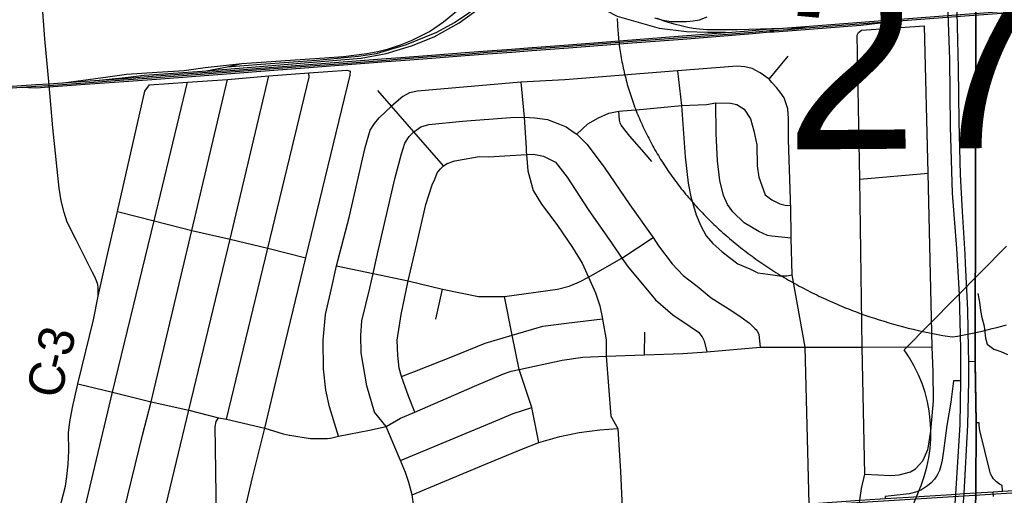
# Model space of a CAD drawing. Extents: x 114604 to 551442, y 316898 to 567001.
# Drawn here: x 164762 to 173075, y 383476 to 387495 of the extents above; entities that cross this region are included whole.
import ezdxf

# ---------------------------------------------------------------- set-up
doc = ezdxf.new("R2010")
doc.units = 0
for name, color, linetype in [('GE_P_Alignment', 7, 'Continuous'), ('GE_P_Alignment_1000_Bearings', 7, 'Continuous'), ('GE_P_Alignment_1000_Cardinal_Points', 7, 'Continuous'), ('GE_P_Alignment_1000_Stations', 7, 'Continuous'), ('GE_P_Alignment_500_Bearings', 7, 'Continuous'), ('GE_P_Alignment_500_Cardinal_Points', 7, 'Continuous'), ('GE_P_Alignment_500_Distances', 7, 'Continuous'), ('GE_P_Alignment_500_Stations', 7, 'Continuous'), ('PM_P_Cells', 7, 'Continuous'), ('PM_P_CL_Double_Solid', 7, 'Continuous'), ('PM_X_Stop_Line', 7, 'Continuous')]:
    doc.layers.add(name, color=color, linetype=linetype)

msp = doc.modelspace()

# ---------------------------------------------------------------- linework, layer by layer
at = {"layer": 'GE_P_Alignment'}
for points in [[(169807.1, 387505.3), (169807.7, 387487.8), (169808.3, 387470.3), (169809.1, 387452.8), (169810.1, 387435.4), (169811.2, 387417.9), (169812.4, 387400.4), (169813.7, 387382.9), (169815.2, 387365.4), (169816.8, 387347.9), (169818.6, 387330.4), (169820.5, 387312.9), (169822.5, 387295.5), (169824.7, 387278), (169827, 387260.5), (169829.5, 387243.1), (169832.1, 387225.6), (169834.8, 387208.2), (169837.7, 387190.7), (169840.7, 387173.3), (169843.8, 387155.9), (169847.1, 387138.4), (169850.5, 387121), (169854, 387103.7), (169857.7, 387086.3), (169861.5, 387068.9), (169865.5, 387051.6), (169869.6, 387034.2), (169873.8, 387016.9), (169878.2, 386999.6), (169882.7, 386982.3), (169887.4, 386965.1), (169892.1, 386947.8), (169897.1, 386930.6), (169902.1, 386913.4), (169907.3, 386896.2), (169912.6, 386879.1), (169918.1, 386861.9), (169923.7, 386844.8), (169929.5, 386827.7), (169935.3, 386810.7), (169941.3, 386793.6), (169947.5, 386776.6), (169953.8, 386759.6), (169960.2, 386742.7), (169966.7, 386725.8), (169973.4, 386708.9), (169980.2, 386692), (169987.2, 386675.2), (169994.3, 386658.4), (170001.5, 386641.6), (170008.9, 386624.9), (170016.4, 386608.2), (170024, 386591.5), (170031.7, 386574.9), (170039.6, 386558.3), (170047.7, 386541.7), (170055.8, 386525.2), (170064.1, 386508.8), (170072.5, 386492.3), (170081.1, 386475.9), (170089.7, 386459.6), (170098.6, 386443.3), (170107.5, 386427), (170116.6, 386410.8), (170125.8, 386394.6), (170135.1, 386378.5), (170144.5, 386362.4), (170154.1, 386346.4), (170163.8, 386330.4), (170173.7, 386314.4), (170183.6, 386298.5), (170193.7, 386282.7), (170204, 386266.9), (170214.3, 386251.2), (170224.8, 386235.5), (170235.4, 386219.8), (170246.1, 386204.3), (170256.9, 386188.7), (170267.9, 386173.3), (170279, 386157.8), (170290.2, 386142.5), (170301.5, 386127.2), (170313, 386111.9), (170324.6, 386096.7), (170336.3, 386081.6), (170348.1, 386066.5), (170360, 386051.5), (170372.1, 386036.6), (170384.3, 386021.7), (170396.6, 386006.8), (170409, 385992.1), (170421.5, 385977.4), (170434.1, 385962.8), (170446.9, 385948.2), (170459.8, 385933.7), (170472.8, 385919.2), (170485.9, 385904.9), (170499.1, 385890.6), (170512.4, 385876.3), (170525.8, 385862.2), (170539.4, 385848.1), (170553, 385834), (170566.8, 385820.1), (170580.7, 385806.2), (170594.7, 385792.4), (170608.8, 385778.7), (170623, 385765), (170637.3, 385751.4), (170651.7, 385737.9), (170666.2, 385724.4), (170680.9, 385711.1), (170695.6, 385697.8), (170710.4, 385684.6), (170725.4, 385671.4), (170740.4, 385658.4), (170755.6, 385645.4), (170770.8, 385632.5), (170786.1, 385619.7), (170801.6, 385606.9), (170817.1, 385594.2), (170832.8, 385581.7), (170848.5, 385569.2), (170864.3, 385556.7), (170880.2, 385544.4), (170896.3, 385532.2), (170912.4, 385520), (170928.6, 385507.9), (170944.9, 385495.9), (170961.3, 385484), (170977.7, 385472.2), (170994.3, 385460.4), (171011, 385448.8), (171027.7, 385437.2), (171044.5, 385425.7), (171061.5, 385414.3), (171078.5, 385403), (171095.6, 385391.8), (171112.7, 385380.7), (171130, 385369.6), (171147.3, 385358.7), (171164.8, 385347.8), (171182.3, 385337.1), (171199.8, 385326.4), (171217.5, 385315.8), (171235.2, 385305.3), (171253.1, 385294.9), (171271, 385284.6), (171288.9, 385274.4), (171307, 385264.3), (171325.1, 385254.3), (171343.3, 385244.3), (171361.5, 385234.5), (171379.9, 385224.7), (171398.3, 385215.1), (171416.8, 385205.6), (171435.3, 385196.1), (171453.9, 385186.7), (171472.6, 385177.5), (171491.3, 385168.3), (171510.1, 385159.3), (171529, 385150.3), (171548, 385141.4), (171567, 385132.7), (171586, 385124), (171605.1, 385115.4), (171624.3, 385106.9), (171643.6, 385098.6), (171662.8, 385090.3), (171682.2, 385082.1), (171701.6, 385074), (171721.1, 385066.1), (171740.6, 385058.2), (171760.2, 385050.4), (171779.8, 385042.7), (171799.5, 385035.2), (171819.2, 385027.7), (171858.8, 385013), (171898.6, 384998.8), (171938.5, 384985), (171978.7, 384971.6), (172019, 384958.6), (172059.5, 384946), (172100.1, 384933.8), (172140.9, 384922.1), (172181.8, 384910.7), (172222.9, 384899.8), (172264, 384889.3), (172305.3, 384879.2), (172346.7, 384869.5), (172388.2, 384860.3), (172429.8, 384851.4), (172471.4, 384843), (172513.2, 384835), (172555, 384827.4), (172596.9, 384820.2), (172638.9, 384813.5)], [(172638.9, 384813.5), (172680.7, 384820.8), (172722.5, 384828.6), (172764.2, 384836.8), (172805.8, 384845.4), (172847.4, 384854.4), (172888.8, 384863.9), (172930.2, 384873.7), (172971.4, 384884), (173012.6, 384894.7), (173053.6, 384905.8), (173094.4, 384917.3)]]:
    msp.add_lwpolyline(points, dxfattribs=at)
at = {"layer": 'GE_P_Alignment_1000_Bearings'}
for p, q in [((166334.9, 387063), (166513.1, 387096.6)), ((166513.1, 387096.6), (166622, 387121.7))]:
    msp.add_line(p, q, dxfattribs=at)
for points in [[(170721.1, 387385.1), (170569.8, 387385.5), (170392.7, 387390.7), (170164.6, 387419), (169809.7, 387520.6), (169541.7, 387659.4), (169382, 387779.3), (169276.9, 387899.7), (169159.7, 388090.2), (169104.1, 388218.7), (169077.1, 388350.1), (169064.3, 388498.4), (169067.5, 388600), (169098.6, 388796.9), (169141.6, 388967.8), (169304.6, 389672.1), (169334.7, 389828.6), (169359.2, 390038.4), (169391.8, 390398.4)], [(166334.9, 387063), (167100.1, 387123.5), (167645.3, 387170.4), (167857.3, 387209.7), (168070.4, 387272.4), (168261.3, 387350.6), (168471.4, 387466.7), (168663.1, 387604.8), (168839, 387770.2), (168982.3, 387953.5), (169156.1, 388228.2), (169251, 388422.9), (169293.9, 388613.4), (169308.2, 388797.1), (169338.7, 389447.1), (169358.2, 389819.7), (169381.5, 390066.1)], [(166513.1, 387096.6), (166800.7, 387118.2), (167266.7, 387152.8), (167623.2, 387186.6), (167775.4, 387208.5), (168027.5, 387284.6), (168284.6, 387388), (168432.4, 387471.1), (168554.3, 387551.4), (168682.4, 387653.9), (168820.9, 387778.6), (168930.5, 387921.3), (169007.9, 388031.3), (169143.1, 388243.2), (169234.2, 388427.5), (169275.8, 388621.8), (169299.4, 388963.1), (169359.2, 390038.4)], [(170721.1, 387385.1), (170774.2, 387389.2), (170946.6, 387403), (171094.9, 387416.8), (171129.8, 387417.5), (171245, 387425.6), (172741.1, 387540.7), (173133.1, 387569.4), (173826.3, 387624.2), (174782.2, 387695.9), (175332.3, 387738.9), (176228, 387803.7), (177511, 387903.1), (177913.7, 387932.6), (178330.8, 387966.6), (182044.2, 388248.3)], [(171402.5, 387424.6), (172742.1, 387527.6), (173134.1, 387556.3), (173827.3, 387611.1), (174783.2, 387682.8), (175333.3, 387725.8), (176229, 387790.6), (177512, 387890), (177914.7, 387919.5), (178331.8, 387953.5), (182045.2, 388235.2)], [(165131.4, 386961.6), (165505.7, 387010.9), (165662.4, 387034.1), (165923.5, 387050.5), (166151.1, 387066.6), (166329.1, 387090.7), (166637.2, 387123.3), (167336, 387173.4), (167494.4, 387184.4), (167691.4, 387207.9), (167786.5, 387224.6), (167874.7, 387247.3), (167976.5, 387281.5), (168076, 387322.6), (168221.6, 387396), (168340.6, 387476.1), (168479.9, 387591.3)], [(171402.5, 387424.6), (170821.5, 387408.8), (170639.8, 387407.5), (170564.4, 387409.6), (170502.5, 387414.6), (170448.7, 387421.2), (170402.2, 387429.6), (170357.7, 387438.6), (170287.3, 387456.2), (170212.3, 387479.2), (170144.5, 387504.4)], [(164455.4, 386903), (164899.4, 386933.1), (165008.1, 386939.7), (165314.9, 386961.6), (165640.8, 386985.8), (165915.2, 387005.7), (166580, 387056.4), (166833, 387075.6), (167092.1, 387095.3), (167457.3, 387122.5), (167856.4, 387153.8), (167979.9, 387162.9), (168240, 387182.4), (168523.1, 387203.6), (168711.3, 387219), (168914.9, 387233.9), (169051.8, 387244.9), (169240.5, 387258.9), (169395.4, 387270.3), (169932.2, 387311.8), (170359, 387344.4), (170775.3, 387376.1), (170947.7, 387390), (171095.7, 387403.7), (171130.4, 387404.4), (171246, 387412.5), (171402.5, 387424.6)], [(164771.3, 386924.4), (164900.2, 386920), (165009, 386926.6), (165086.4, 386932.1), (165315.8, 386948.5), (165641.8, 386972.8), (165916.1, 386992.6), (166581, 387043.3), (166834, 387062.5), (167093.1, 387082.3), (167458.3, 387109.4), (167857.4, 387140.7), (167980.9, 387149.8), (168241, 387169.3), (168524.1, 387190.6), (168712.3, 387205.9), (168915.9, 387220.8), (169052.8, 387231.8), (169241.5, 387245.8), (169396.4, 387257.2), (169933.2, 387298.7), (170360, 387331.3), (170776.3, 387363), (170948.9, 387376.9), (171096.4, 387390.6), (171131, 387391.3), (171246.9, 387399.4), (171864.3, 387446.9), (172123.4, 387480)], [(164454.5, 386916.1), (164898.5, 386946.2), (165007.2, 386952.8), (165313.9, 386974.7), (165639.9, 386998.9), (165914.2, 387018.8), (166579, 387069.4), (166832, 387088.6), (167091.1, 387108.4), (167456.3, 387135.6), (167855.4, 387166.9), (167978.9, 387175.9), (168239.1, 387195.5), (168522.1, 387216.7), (168710.3, 387232), (168913.9, 387246.9), (169050.8, 387257.9), (169239.6, 387272), (169394.4, 387283.3), (169931.2, 387324.9), (170358, 387357.5), (170721.1, 387385.1)], [(165403.3, 386981.4), (165655.5, 387006.3), (165812.9, 387027), (166302.3, 387060.5), (166334.9, 387063)], [(139976.5, 381530.3), (141701.6, 381686.5), (142931.4, 381776.7), (145058.8, 381883.3), (151605.9, 382247), (160057.2, 382729.4), (166949.7, 383110), (174406.2, 383574.4), (180366.1, 383984.7)]]:
    msp.add_lwpolyline(points, dxfattribs=at)
at = {"layer": 'GE_P_Alignment_1000_Cardinal_Points'}
for p, q in [((171868.1, 387407.3), (172402.3, 387442.8)), ((171090.9, 386992.6), (171249, 387185.2)), ((165896.1, 385795), (166177.7, 386967.3)), ((171854.1, 386146), (172432, 386197.9)), ((168276.5, 384963.5), (168330.9, 385216.4)), ((170036.7, 384662.4), (170040.7, 384853)), ((166441.5, 384131.7), (166508.5, 384118))]:
    msp.add_line(p, q, dxfattribs=at)
for points in [[(171875.9, 384726.6), (171854.1, 386146), (171833.9, 387364.8), (171844.7, 387386.5), (171868.1, 387407.3)], [(172431.8, 383873.7), (172454.1, 384017.4), (172478, 384274), (172475.9, 384518.5), (172465.7, 384729), (172432, 386197.9), (172402.3, 387442.8)], [(171090.9, 386992.6), (171014.8, 387046.7), (170946.6, 387082.7), (170884.6, 387096.7), (170820.5, 387100.6), (170315.7, 387062), (169364.8, 386986.9), (168991.9, 386966.5), (168119.3, 386889.6), (168053.2, 386875.5), (167997.2, 386845.3), (167901.1, 386763.1)], [(165858.3, 386945.4), (166177.7, 386967.3), (166516.9, 386989.5), (166865.8, 387019), (167204.3, 387045.6), (167524.3, 387069.3), (167554.3, 387060.9)], [(165872.7, 384265.6), (166216.3, 385713.7), (166516.9, 386989.5)], [(166189.5, 384195.8), (166538.9, 385639.9), (166865.8, 387019)], [(166508.5, 384118), (166858.1, 385563.4), (167204.6, 387008.6), (167204.3, 387045.6)], [(166603.6, 383085.8), (166648.5, 383288.4), (166725.2, 383614.2), (166832.3, 384042.1), (166942.7, 384505.7), (167178.5, 385482.4), (167553.1, 387026.8), (167554.3, 387060.9)], [(170315.7, 387062), (170350.1, 386769.5), (170380.4, 386334.5), (170404.5, 386112.1), (170428.6, 385997.8), (170474.7, 385845.6), (170512.8, 385751.4), (170558.9, 385667.3), (170613, 385603.2), (170689.2, 385535.1), (170755.2, 385485), (170825.4, 385433), (170925.5, 385389), (170993.6, 385355), (171119.8, 385339.1), (171177.8, 385331.1), (171239.9, 385331.2), (171282.7, 385339.1)], [(171270, 385977.7), (171253.4, 386479.7), (171253.3, 386660.1), (171247.2, 386740.2), (171217.1, 386834.4), (171183, 386882.5), (171153, 386922.5), (171112.9, 386962.6), (171090.9, 386992.6)], [(165425.7, 385158.6), (165502.2, 385509.8), (165588.3, 385872.8), (165819.3, 386891), (165858.3, 386945.4)], [(168991.9, 386966.5), (169022.5, 386672), (169037.7, 386408.1)], [(168339.9, 386258.4), (168089.4, 386546.5), (167901.1, 386763.1), (167784.9, 386897.3)], [(167454.3, 383974.6), (167377.7, 384223), (167345.6, 384365.3), (167327.5, 384545.7), (167323.4, 384786.2), (167343.3, 385004.7), (167395.3, 385223.2), (167437.8, 385414.1), (167543.1, 385822.7), (167679, 386414.1), (167721, 386562.4), (167757, 386616.6), (167797, 386664.7), (167901.1, 386763.1)], [(169466.4, 386527), (169559.2, 386614.3), (169649.3, 386664.5), (169735.4, 386704.7), (169821.5, 386721), (170029.7, 386739.1), (170350.1, 386769.5), (170560.4, 386777.7), (170640.4, 386791.8)], [(171276.9, 385647.7), (171193.7, 385655.9), (171111.6, 385665.8), (171075.6, 385669.7), (171003.4, 385705.8), (170879.3, 385777.8), (170783.1, 385869.9), (170737, 385934), (170702.9, 386008.2), (170672.8, 386136.4), (170654.7, 386302.7), (170642.6, 386533.2), (170640.4, 386791.8)], [(170640.4, 386791.8), (170764.6, 386789.9), (170816.7, 386777.9), (170878.7, 386737.9), (170930.9, 386657.7), (170961, 386555.6), (170985.1, 386437.3), (170989.1, 386261), (171001.2, 386162.7), (171055.4, 386014.5), (171113.4, 385972.5), (171179.5, 385938.5), (171225.6, 385926.4), (171271.7, 385924.8)], [(168089.4, 386546.5), (168147.5, 386588.9), (168217.6, 386609), (168499.9, 386637.4), (168904.4, 386667.8), (169022.5, 386672)], [(169022.5, 386672), (169110.6, 386666), (169216.8, 386652.1), (169320.9, 386612.1), (169375, 386588.1), (169443.1, 386542.1), (169466.4, 386527), (169551.3, 386444), (169697.6, 386249.7), (169914, 385931.2), (170102.4, 385664.8), (170109.8, 385653.8), (170156.5, 385584.7), (170270.7, 385430.5), (170364.9, 385334.3), (170483.1, 385242.2), (170601.2, 385144.1), (170773.5, 385034.1), (170853.6, 384980), (170923.8, 384930), (170967.8, 384885.9), (170985.9, 384871.9), (171003.9, 384833.9), (171014, 384727.6)], [(170098, 386296.2), (170033.9, 386372.3), (169913.7, 386510.5), (169839.5, 386602.6), (169831.5, 386622.6), (169827.5, 386644.7), (169821.5, 386721)], [(167745.7, 385349), (167783.6, 385516.2), (167929.4, 386149.8), (167985.4, 386362.3), (168013.4, 386452.5), (168051.4, 386506.7), (168089.4, 386546.5)], [(169037.7, 386408.1), (169039.2, 386381.7), (169040.7, 386355.3), (169052.8, 386217), (169096.9, 386050.7), (169167.1, 385934.5), (169297.3, 385764.3), (169429.6, 385569.9), (169509.8, 385437.7), (169564.8, 385318), (169624, 385185.3), (169660.1, 385077.1), (169681.4, 384967.2), (169682.2, 384962.9), (169712.3, 384790.5), (169714.4, 384650.2)], [(168339.9, 386258.4), (168369.9, 386280.5), (168436, 386300.6), (168640.2, 386338.9), (168718.3, 386336.9), (168858.5, 386343.1), (169040.7, 386355.3)], [(169040.7, 386355.3), (169100.8, 386359.3), (169184.9, 386341.4), (169287, 386289.4), (169383.2, 386163.2), (169561.6, 385890.8), (169764, 385600.3), (169847.1, 385480.1), (169894.2, 385412.1), (170128.7, 385127.7), (170276.9, 385001.5), (170423.2, 384903.4), (170493.3, 384855.4), (170523.3, 384815.3), (170541.3, 384781.3), (170563.4, 384689.1)], [(168096.7, 384179.6), (168044.5, 384313.8), (167986.1, 384479.2), (167966.3, 384550.3), (167954.2, 384658.5), (167950.2, 384786.8), (167982.1, 385003.3), (168042, 385288), (168115.9, 385600.7), (168191.9, 385933.6), (168243.9, 386098), (168265.9, 386148.1), (168285.9, 386200.2), (168313.9, 386234.3), (168339.9, 386258.4)], [(171394.8, 384727.7), (171282.7, 385339.1), (171276.9, 385647.7), (171271.7, 385924.8), (171271.2, 385942.2), (171270, 385977.7)], [(165588.3, 385872.8), (165896.1, 385795), (166216.3, 385713.7), (166538.9, 385639.9), (166858.1, 385563.4), (167178.5, 385482.4)], [(165225.8, 382987.8), (165234.5, 383023.5), (165275.2, 383209), (165545.1, 384346.8), (165896.1, 385795)], [(169468.7, 385271.3), (169487.8, 385279.4), (169564.8, 385318), (169847.1, 385480.1), (170109.8, 385653.8)], [(167437.8, 385414.1), (167745.7, 385349), (168042, 385288)], [(167876.6, 384009.9), (167856.3, 384057.9), (167758.3, 384177.3), (167692, 384399.7), (167645.8, 384678.3), (167641.8, 384826.6), (167651.7, 384948.9), (167717.7, 385225.5), (167745.7, 385349)], [(168042, 385288), (168330.9, 385216.4), (168634.8, 385154.3), (168737, 385154.4), (168855.1, 385154.5), (169301.6, 385217.1), (169401.7, 385243.2), (169468.7, 385271.3)], [(169144.5, 383921.5), (169086.7, 384217.8), (168977.6, 384539.3), (168919.3, 384829.8), (168855.1, 385154.5)], [(167986.1, 384479.2), (168096.5, 384522.4), (168428.8, 384655), (168693.1, 384761.5), (168843.3, 384805.7), (168919.3, 384829.8), (169177.6, 384904.2), (169401.9, 384934.5), (169681.4, 384967.2)], [(167037.8, 383985.3), (167043.4, 383984.1), (167213.7, 383956.2), (167361.9, 383956.4), (167385.9, 383958.4), (167454.3, 383974.6), (167714.3, 384024.9), (167856.3, 384057.9), (167976.5, 384127.4), (168096.7, 384179.6), (168601.2, 384398.6), (168845.4, 384501), (168911.5, 384525.2), (168977.6, 384539.3), (169342, 384617.8), (169516.2, 384644), (169714.4, 384650.2), (170036.7, 384662.4), (170361.2, 384674.9), (170563.4, 384689.1), (171014, 384727.6), (171394.8, 384727.7), (171635.3, 384727.2)], [(171428, 383367.5), (171427.1, 383405.1), (171394.8, 384727.7)], [(171635.3, 384727.2), (171875.9, 384726.6), (172465.7, 384729)], [(171848.5, 383390.5), (171854.7, 383433.7), (171868.8, 383533.2), (171897.6, 383654.2), (171875.9, 384726.6)], [(169714.4, 384650.2), (169752.7, 384145.1), (169810.8, 384039), (169833.5, 383676.2), (169851.5, 383309.3), (169853.5, 383268.6)], [(165251.7, 384417.5), (165545.1, 384346.8), (165872.7, 384265.6), (166189.5, 384195.8), (166441.5, 384131.7)], [(165571.9, 383024.6), (165612.5, 383224.3), (165798.5, 383984.8), (165872.7, 384265.6)], [(165934.4, 383047.5), (165938.4, 383124), (165961.6, 383246.5), (166189.5, 384195.8)], [(167977.9, 383770.2), (168815.3, 384118.5), (168929.6, 384168), (169086.7, 384217.8)], [(166436.7, 383076.3), (166424.1, 383276.9), (166414.1, 383878), (166411, 384055.1), (166421, 384100.4), (166441.5, 384131.7)], [(166508.5, 384118), (166832.3, 384042.1), (166986.8, 383995.8), (167037.8, 383985.3)], [(168085.9, 383164.3), (168091.4, 383204.2), (168097, 383244.1), (168091, 383379.4), (168075.4, 383479.1), (168048, 383583.1), (168019.5, 383667.4), (167977.9, 383770.2), (167876.6, 384009.9)], [(168075.4, 383479.1), (168694.9, 383739.6), (169001.7, 383866.7), (169144.5, 383921.5), (169323.2, 383972.2), (169486.2, 384005.5), (169658.7, 384028.8), (169810.8, 384039)], [(171897.6, 383654.2), (172117.9, 383644.2), (172187.9, 383648.3), (172284.1, 383674.4), (172326.1, 383700.5), (172388.1, 383766.8), (172402.1, 383798.8), (172430.1, 383863), (172431.8, 383873.7)]]:
    msp.add_lwpolyline(points, dxfattribs=at)
at = {"layer": 'GE_P_Alignment_1000_Stations'}
msp.add_line((172982.5, 383505.9), (173060.9, 383511.5), dxfattribs=at)
for points in [[(173060.9, 383511.5), (173292.5, 383526.2), (173726.5, 383559), (174056.1, 383581.3), (174395.2, 383603.8), (174902.3, 383637.3), (175187.6, 383654.5), (176315.3, 383732.1), (176459.4, 383709.3)], [(172630, 383482.8), (172665.4, 383484.9), (172736.3, 383490.4), (172836, 383496.9), (172982.5, 383505.9)], [(166603.6, 383085.8), (166614.2, 383092.8), (166637.3, 383102.1), (167008.9, 383129.5), (167396.6, 383160.9), (167509.1, 383168.9), (167766.6, 383184.5), (168091.4, 383204.2), (168695, 383236.9), (168974.5, 383254.9), (169254, 383271.8), (169535.4, 383290.5), (169851.5, 383309.3), (170297.2, 383336.8), (170663.5, 383358.8), (171109.8, 383386.8), (171427.1, 383405.1), (171854.7, 383433.7), (171942.3, 383439.9), (172070.6, 383448.3), (172264.9, 383461.3), (172630, 383482.8)]]:
    msp.add_lwpolyline(points, dxfattribs=at)
at = {"layer": 'GE_P_Alignment_500_Bearings'}
for points in [[(165377.9, 385358.1), (165241.2, 385629), (165163, 385783.6), (165138.2, 385865), (165111.5, 385962.6), (165093.7, 386071), (165040.7, 386580.9), (165009.4, 386940.2), (164975.2, 387331.9), (164945.2, 387715.6), (164932.4, 387845.1)], [(165010.4, 382972.8), (165020.2, 383011.9), (165066.7, 383197.9), (165115.3, 383422.2), (165147.2, 383551.8), (165158.7, 383634.9), (165172.3, 383739), (165176.9, 383850.3), (165174, 384002.7), (165185.9, 384096), (165208.3, 384218.2), (165251.7, 384417.5), (165384.1, 384958.4), (165425.7, 385158.6), (165425.2, 385229.5), (165420.6, 385258.2), (165411.4, 385288.6), (165396.8, 385320.8), (165377.9, 385358.1)]]:
    msp.add_lwpolyline(points, dxfattribs=at)
at = {"layer": 'GE_P_Alignment_500_Cardinal_Points'}
for p, q in [((173093.9, 385582.1), (172230.1, 384705.6)), ((172838.1, 384088.7), (172829.5, 384592.1)), ((172984.7, 383465), (172982.5, 383505.9))]:
    msp.add_line(p, q, dxfattribs=at)
for points in [[(172829.5, 384592.1), (172829.2, 384604.7), (172775.6, 384606.4)], [(172709.5, 384444), (172645.2, 384442.1), (172623.6, 384263.1), (172589.7, 384066.9), (172562, 383851.1), (172550.7, 383772.2), (172540.5, 383726.2), (172526.9, 383685), (172507.1, 383645.2), (172486.8, 383611.6), (172457.9, 383581.7), (172427.9, 383556.2), (172402.7, 383538.3), (172375.6, 383523.3), (172337.5, 383504.9), (172270.7, 383489.1), (172069.1, 383467.1), (172070.6, 383448.3)], [(172813.6, 383031), (172816.3, 383124.3), (172834.9, 383456), (172836, 383496.9), (172838.1, 384088.7)], [(173060.9, 383511.5), (173058.3, 383559), (173033.8, 383570.4), (173008, 383589.1), (172984.8, 383613.6), (172968.5, 383638.7), (172959.9, 383657.3), (172952.4, 383681), (172868.4, 384024.4), (172863, 384066.3), (172862.4, 384089.1), (172838.1, 384088.7)]]:
    msp.add_lwpolyline(points, dxfattribs=at)
for centre, start, end in [((171237.2, 383999.7), 334.95983, 35.41363), ((173447.2, 382974), 155.24462, 271.05096)]:
    msp.add_arc(centre, 1218.2, start, end, dxfattribs=at)
at = {"layer": 'GE_P_Alignment_500_Distances'}
for points in [[(172735.5, 373316.5), (172743.8, 375149.5), (172783.4, 378654), (172785.5, 379134.7), (172790.5, 380011.3), (172806.8, 382842.1), (172812.1, 383022.8), (172815.2, 383127.1), (172833.7, 383458.8), (172834.8, 383499.7), (172836.9, 384091.5), (172828, 384607.5), (172834.2, 387596.6)], [(172834.2, 387596.6), (172828, 384607.5), (172836.9, 384091.5), (172834.8, 383499.7), (172833.7, 383458.8), (172815.2, 383127.1), (172812.1, 383022.8), (172806.8, 382842.1), (172790.5, 380011.3), (172785.5, 379134.7), (172783.4, 378654), (172743.8, 375149.5), (172735.5, 373316.5)]]:
    msp.add_lwpolyline(points, dxfattribs=at)
at = {"layer": 'GE_P_Alignment_500_Stations'}
for points in [[(172496, 382201.5), (172554.4, 382525.4), (172581.9, 382734.4), (172647.6, 383240.3), (172663, 383446), (172665.4, 383484.9), (172702.9, 384073.4), (172709.5, 384444), (172709, 384713.5), (172696.5, 385172), (172674, 385562.2), (172638.2, 386028.6), (172620.2, 386590.2), (172616.1, 387161.1), (172594.8, 387711.1), (172592.3, 388214.9), (172584.7, 388634.1), (172581.9, 389013.9), (172598.5, 389290.8), (172614, 389573.1), (172625.4, 390022.1), (172641.1, 390446.5)], [(172743.3, 385514.2), (172722.7, 385872.7), (172705.4, 386187.6), (172693, 386632.3), (172689.7, 387086.2), (172675, 387679.1), (172669.2, 388165.5), (172664.1, 388545.3), (172663.1, 388847.6), (172661.8, 389185.8), (172662, 389207.3)], [(172773.5, 384713.1), (172766.9, 385043.8), (172747.9, 385434), (172743.3, 385514.2)], [(172722.9, 383338.9), (172734.1, 383450.6), (172736.3, 383490.4), (172768.2, 384071), (172774.7, 384441.6), (172775.6, 384606.4), (172773.5, 384713.1)]]:
    msp.add_lwpolyline(points, dxfattribs=at)
at = {"layer": 'PM_P_Cells'}
for points in [[(170121.5, 387511), (170191.4, 387490.7), (170263.4, 387480.4), (170391.4, 387479.9), (170447.5, 387483.7), (170501.5, 387493.5), (170565.6, 387519.3)], [(172851.8, 385181), (172865.3, 385106.8), (172872.9, 385038.6), (172884.5, 384978.4), (172904, 384906.1), (172911.7, 384853.9), (172917.4, 384803.7), (172929.1, 384753.6), (172986.8, 384711.1), (173044.7, 384690.7), (173102.6, 384664.3)]]:
    msp.add_lwpolyline(points, dxfattribs=at)

# ---------------------------------------------------------------- texts
at = {"layer": 'GE_P_Alignment'}
msp.add_text('270', height=1500.08, rotation=0.41268, dxfattribs=at).set_placement((171226.8, 386397.2))
at = {"layer": 'PM_P_CL_Double_Solid'}
for s, rotation, p in [('3', 76.27847, (165188.9, 384637.4)), ('-', 76.37012, (165160.2, 384518.9)), ('C', 77.16402, (165106.1, 384281.5))]:
    msp.add_text(s, height=300, rotation=rotation, dxfattribs=at).set_placement(p)
at = {"layer": 'PM_X_Stop_Line'}
for s, p in [('-', (172621.8, 387156.8)), ('.', (172621.8, 387156.8)), (',', (172621.8, 387156.8)), ('270', (172317.8, 386947.6))]:
    msp.add_text(s, height=1, rotation=0.41268, dxfattribs=at).set_placement(p)

doc.saveas('drawing.dxf')
